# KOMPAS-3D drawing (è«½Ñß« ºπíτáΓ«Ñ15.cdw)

Referenced files in C:\Documents and Settings\Мы\Рабочий стол\Чертежи деталей\Компас\: Колесо зубчатое.cdw
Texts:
  Колесо зубчатое
  Aleksey
  Home
  125 1 126 1 127 1 128 0 50 1|SPDS|125 1 126 1 127 1 128 0 50 1
  129 1 130 1 131 1 132 0 50 1|SPDS|129 1 130 1 131 1 132 0 50 1
  max
  Js9
  Ra3.2
  Ra1.6
  Ra1.25
  Ra12,5
  Модуль
  Число зубьев
  Угол наклона
  Направление линии зуба
  Нормальный исходный
  контур
  Коэффициент смещения
  Степень точности
  Делительный диаметр
  левое
  ГОСТ
  Длина общей нормали
  Термообработка улучшение НВ 269..302
  Радиусы скруглений 2 мм мах
  Сталь 45 ГОСТ 1050-88
  ДГТУ
  Колесо зубчатое               -
Dimensions and other numbers on the sheet: 45; 0.008; 0.025; 0,4; 49; 12; 0.02; 236; 209; 151; 93; 1,5; 2 фаски; 18; 4 отв.; 2,5; 1; 15; 46; 1.5; 155; 13755-81; 0; 8 - В; 235; 85,45; 1:1; 0,55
